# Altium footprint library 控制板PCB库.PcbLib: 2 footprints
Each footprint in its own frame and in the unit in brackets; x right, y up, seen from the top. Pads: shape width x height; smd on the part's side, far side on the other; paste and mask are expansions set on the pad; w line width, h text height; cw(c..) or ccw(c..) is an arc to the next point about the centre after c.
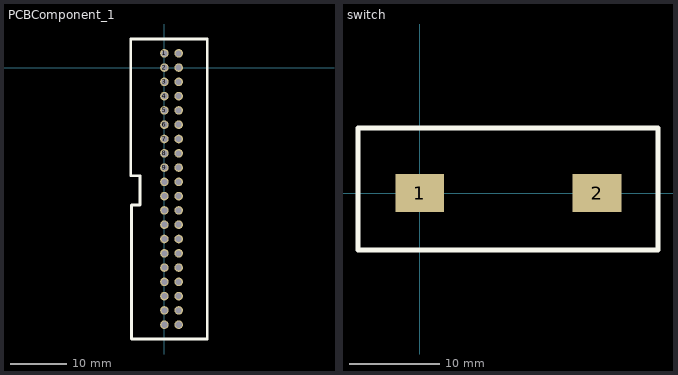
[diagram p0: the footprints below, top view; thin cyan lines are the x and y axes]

## PCBComponent_1 [mil]
pads (40):
  round 60 hole 41.73: 1(0,100) 2(0,0) 3(0,-100) 4(0,-200) 5(0,-300) 6(0,-400) 7(0,-500) 8(0,-600) 9(0,-700) 10(0,-800) 11(0,-900) 12(0,-1000) 13(0,-1100) 14(0,-1200) 15(0,-1300) 16(0,-1400) 17(0,-1500) 18(0,-1600) 19(0,-1700) 21(100,100) 22(100,0) 23(100,-100) 24(100,-200) 25(100,-300) 26(100,-400) 27(100,-500) 28(100,-600) 29(100,-700) 30(100,-800) 31(100,-900) 32(100,-1000) 33(100,-1100) 34(100,-1200) 35(100,-1300) 36(100,-1400) 37(100,-1500) 38(100,-1600) 39(100,-1700)
  round 60 hole 42.52: 20(0,-1800) 40(100,-1800)
Top Overlay:
  lines w20: -231,-965 -231,-1900 300,-1900 300,200 -236,200 -236,-757 -171,-757 -171,-963 -230,-963

## switch [mm]
pads (2):
  rect 5.4x4.2 smd: 1(0,0) 2(19.685,0)
Top Overlay:
  lines w0.508: -6.833,7.214 -6.833,-6.325 26.441,-6.325 26.441,7.214 -4.115,7.214 -6.68,7.214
